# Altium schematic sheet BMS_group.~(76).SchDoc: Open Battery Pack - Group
size A3; Author: Morgane Vallée; Revision: 1.0; SheetNumber: 2; SheetTotal: 3
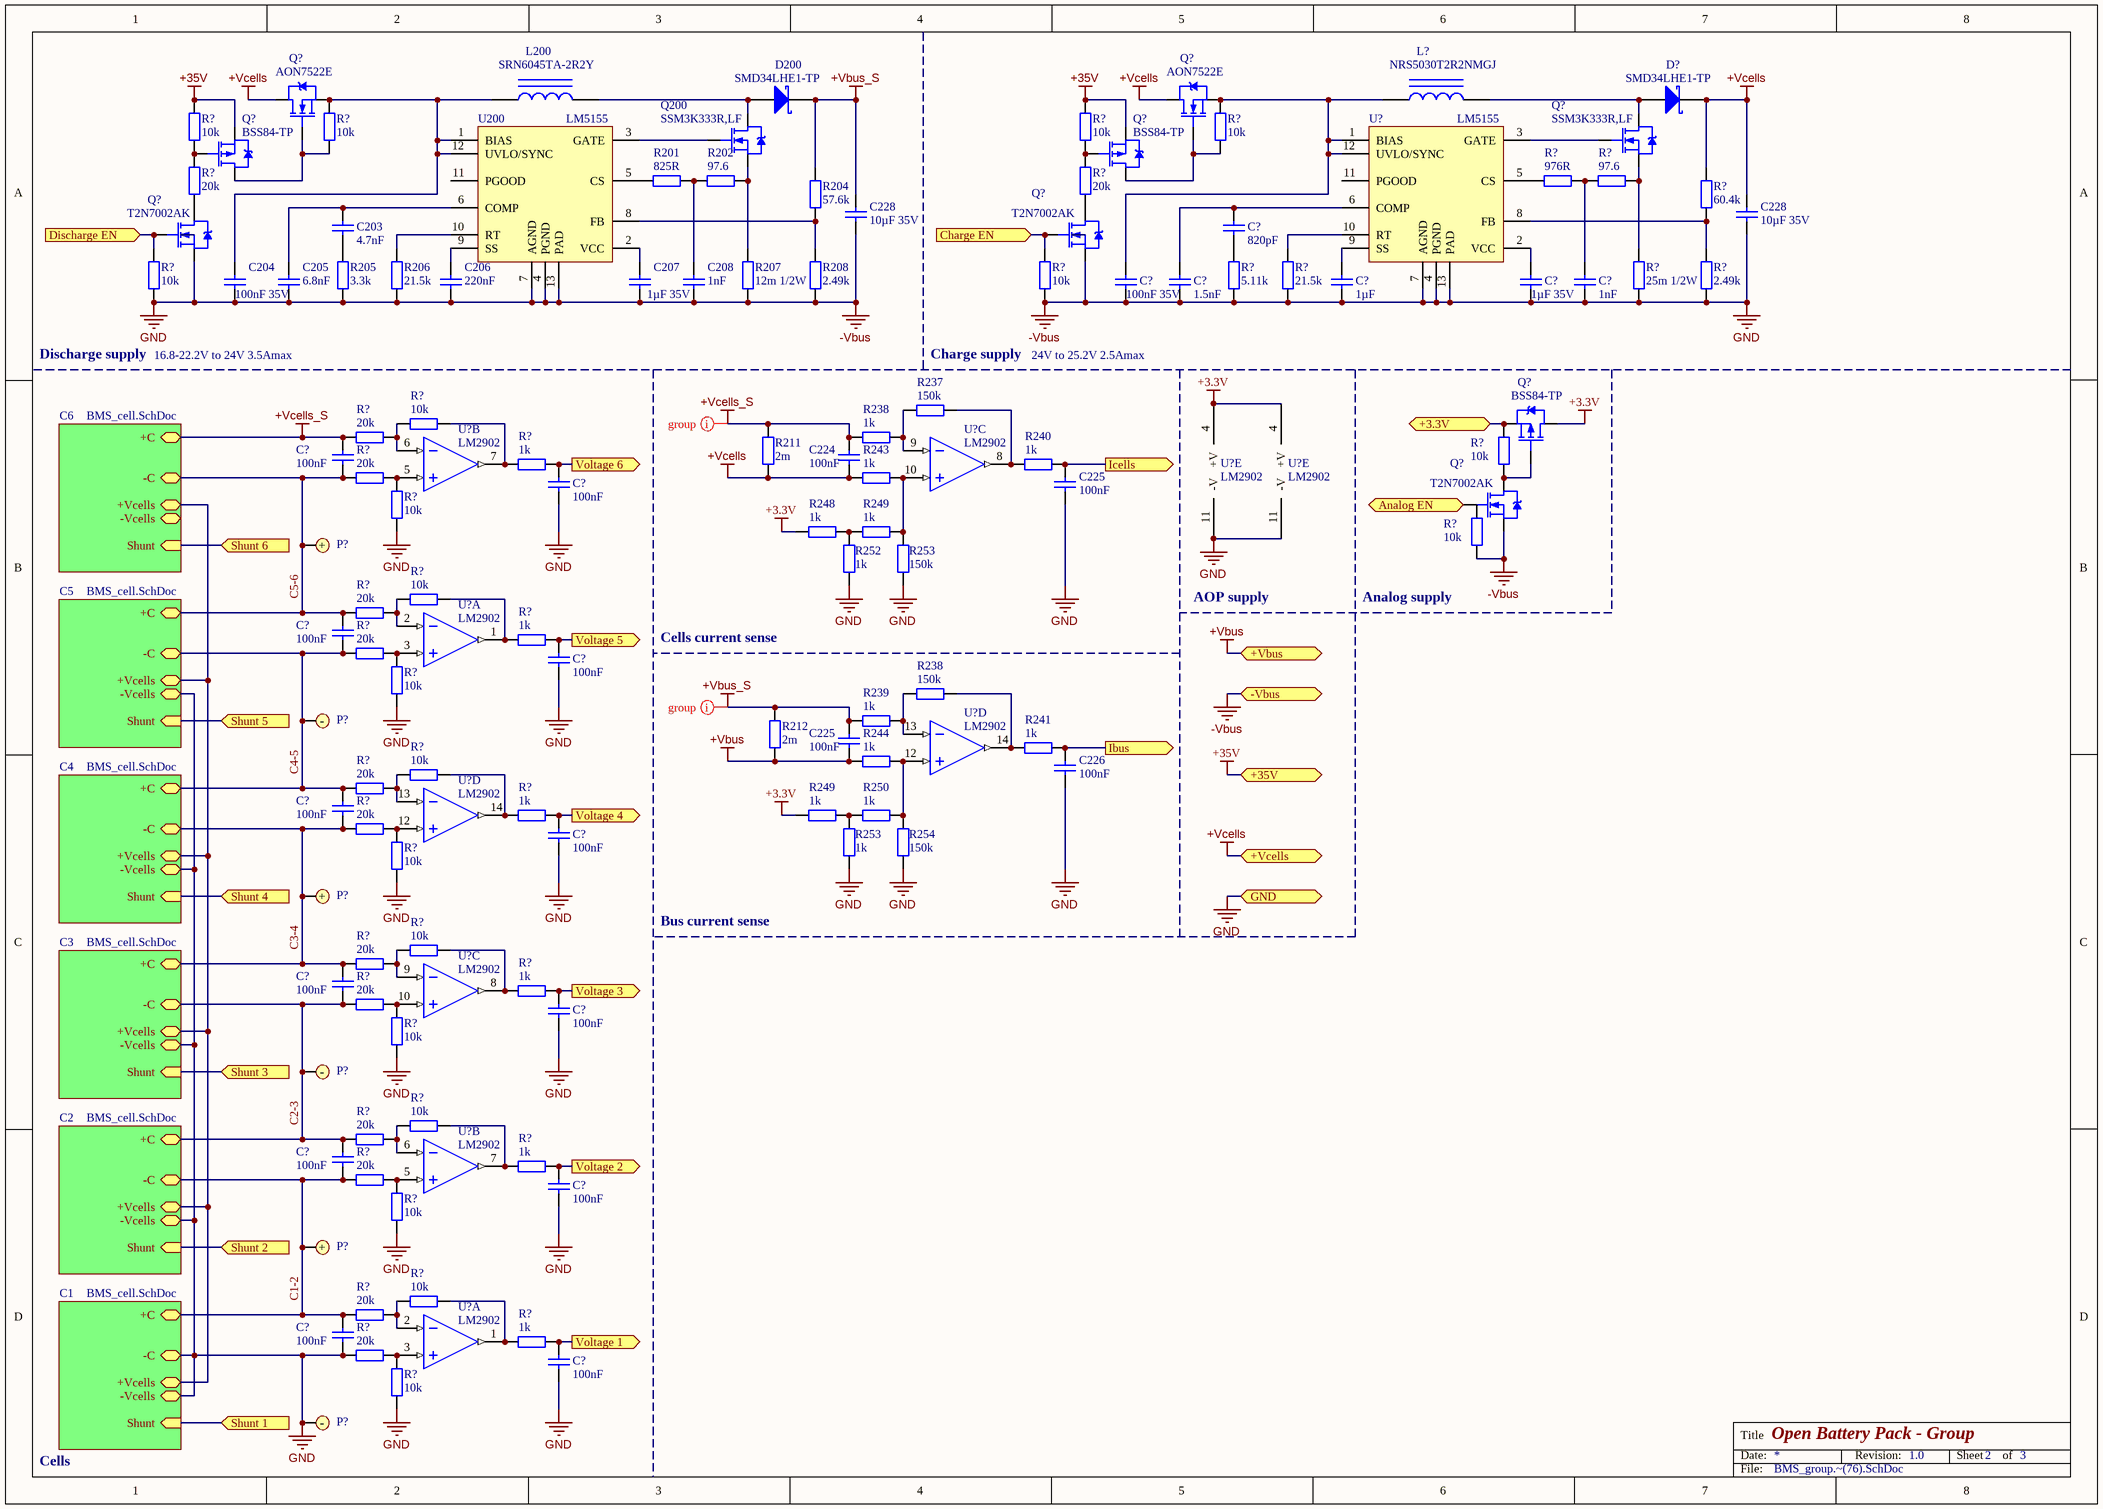
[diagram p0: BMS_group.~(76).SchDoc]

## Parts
(Parts that share a designator on the sheet are numbered #1, #2 ... from top to bottom, then left to right.)
C203  4.7nF  [C0603]
C204  100nF 35V  [C0603]
C205  6.8nF  [C0603]
C206  220nF  [C0603]
C207  1µF 35V  [C0805]
C208  1nF  [C0603]
C224  100nF  [C0603]
C225#1  100nF  [C0603]
C225#2  100nF  [C0603]
C226  100nF  [C0603]
C228#1  10µF 35V  [C0603]
C228#2  10µF 35V  [C0603]
C?#1  820pF  [C0603]
C?#2  100nF 35V  [C0603]
C?#3  1.5nF  [C0603]
C?#4  1µF  [C0603]
C?#5  1µF 35V  [C0805]
C?#6  1nF  [C0603]
C?#7  100nF  [C0603]
C?#8  100nF  [C0603]
C?#9  100nF  [C0603]
C?#10  100nF  [C0603]
C?#11  100nF  [C0603]
C?#12  100nF  [C0603]
C?#13  100nF  [C0603]
C?#14  100nF  [C0603]
C?#15  100nF  [C0603]
C?#16  100nF  [C0603]
C?#17  100nF  [C0603]
C?#18  100nF  [C0603]
D200  SMD34LHE1-TP  [SOD-123H]
D?  SMD34LHE1-TP  [SOD-123H]
L200  SRN6045TA-2R2Y  [SELF_SMD_8x8]
L?  NRS5030T2R2NMGJ  [SELF_SMD_8x8]
P?#1  Bat+  [Keystone 241]  (value not drawn)
P?#2  Bat-  [Keystone 2993]  (value not drawn)
P?#3  Bat+  [Keystone 241]  (value not drawn)
P?#4  Bat-  [Keystone 2993]  (value not drawn)
P?#5  Bat+  [Keystone 241]  (value not drawn)
P?#6  Bat-  [Keystone 2993]  (value not drawn)
Q200  SSM3K333R,LF  [TI SOT-23-3 DBZ]
Q?#1  AON7522E  [DIODES SOT-23-3]
Q?#2  AON7522E  [DIODES SOT-23-3]
Q?#3  SSM3K333R,LF  [TI SOT-23-3 DBZ]
Q?#4  BSS84-TP  [DIODES SOT-23-3]
Q?#5  BSS84-TP  [DIODES SOT-23-3]
Q?#6  T2N7002AK  [DIODES SOT-23-3]
Q?#7  T2N7002AK  [DIODES SOT-23-3]
Q?#8  BSS84-TP  [DIODES SOT-23-3]
Q?#9  T2N7002AK  [DIODES SOT-23-3]
R201  825R  [R0603]
R202  97.6  [R0603]
R204  57.6k  [R0603]
R205  3.3k  [R0603]
R206  21.5k  [R0603]
R207  12m 1/2W  [R1206]
R208  2.49k  [R0603]
R211  2m  [R1206]
R212  2m  [R1206]
R237  150k  [R0603]
R238#1  1k  [R0603]
R238#2  150k  [R0603]
R239  1k  [R0603]
R240  1k  [R0603]
R241  1k  [R0603]
R243  1k  [R0603]
R244  1k  [R0603]
R248  1k  [R0603]
R249#1  1k  [R0603]
R249#2  1k  [R0603]
R250  1k  [R0603]
R252  1k  [R0603]
R253#1  150k  [R0603]
R253#2  1k  [R0603]
R254  150k  [R0603]
R?#1  10k  [R0603]
R?#2  10k  [R0603]
R?#3  10k  [R0603]
R?#4  10k  [R0603]
R?#5  20k  [R0603]
R?#6  20k  [R0603]
R?#7  976R  [R0603]
R?#8  97.6  [R0603]
R?#9  60.4k  [R0603]
R?#10  10k  [R0603]
R?#11  10k  [R0603]
R?#12  5.11k  [R0603]
R?#13  21.5k  [R0603]
R?#14  25m 1/2W  [R1206]
R?#15  2.49k  [R0603]
R?#16  10k  [R0603]
R?#17  20k  [R0603]
R?#18  10k  [R0603]
R?#19  1k  [R0603]
R?#20  20k  [R0603]
R?#21  10k  [R0603]
R?#22  10k  [R0603]
R?#23  10k  [R0603]
R?#24  20k  [R0603]
R?#25  1k  [R0603]
R?#26  20k  [R0603]
R?#27  10k  [R0603]
R?#28  10k  [R0603]
R?#29  20k  [R0603]
R?#30  1k  [R0603]
R?#31  20k  [R0603]
R?#32  10k  [R0603]
R?#33  10k  [R0603]
R?#34  20k  [R0603]
R?#35  1k  [R0603]
R?#36  20k  [R0603]
R?#37  10k  [R0603]
R?#38  10k  [R0603]
R?#39  20k  [R0603]
R?#40  1k  [R0603]
R?#41  20k  [R0603]
R?#42  10k  [R0603]
R?#43  10k  [R0603]
R?#44  20k  [R0603]
R?#45  1k  [R0603]
R?#46  20k  [R0603]
R?#47  10k  [R0603]
U200  LM5155  [TI WSON-12]
U?#1  LM5155  [TI WSON-12]
U?#2  LM2902  [Atmel SO-14 14S1]  (part B of 5)
U?#3  LM2902  [Atmel SO-14 14S1]  (part C of 5)
U?#4  LM2902  [Atmel SO-14 14S1]  (part E of 5)
U?#5  LM2902  [Atmel SO-14 14S1]  (part E of 5)
U?#6  LM2902  [Atmel SO-14 14S1]  (part A of 5)
U?#7  LM2902  [Atmel SO-14 14S1]  (part D of 5)
U?#8  LM2902  [Atmel SO-14 14S1]  (part D of 5)
U?#9  LM2902  [Atmel SO-14 14S1]  (part C of 5)
U?#10  LM2902  [Atmel SO-14 14S1]  (part B of 5)
U?#11  LM2902  [Atmel SO-14 14S1]  (part A of 5)

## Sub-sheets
C1 = BMS_cell.SchDoc: -C, +C, +Vcells, -Vcells, Shunt (in)
C2 = BMS_cell.SchDoc: -C, +C, +Vcells, -Vcells, Shunt (in)
C3 = BMS_cell.SchDoc: -C, +C, +Vcells, -Vcells, Shunt (in)
C4 = BMS_cell.SchDoc: -C, +C, +Vcells, -Vcells, Shunt (in)
C5 = BMS_cell.SchDoc: -C, +C, +Vcells, -Vcells, Shunt (in)
C6 = BMS_cell.SchDoc: -C, +C, +Vcells, -Vcells, Shunt (in)

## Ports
+3.3V, +35V, +Vbus, +Vcells, -Vbus, Analog EN (in), Charge EN (in), Discharge EN (in), GND, Ibus (out), Icells (out), Shunt 1 (in), Shunt 2 (in), Shunt 3 (in), Shunt 4 (in), Shunt 5 (in), Shunt 6 (in), Voltage 1 (out), Voltage 2 (out), Voltage 3 (out), Voltage 4 (out), Voltage 5 (out), Voltage 6 (out)

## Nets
+3.3V: Q?#8.3(D) R248.2 R249#2.2 U?#4.4(+V) U?#5.4(+V)
+35V: Q?#4.2(S) Q?#5.2(S) R?#1.2 R?#3.2 ; port +35V
+Vbus: C225#2.2 R212.1 R244.2 ; port +Vbus
+Vbus_S: C225#2.1 C228#1.1 D200.3(K) R204.2 R212.2 R239.1
+Vcells: C224.2 C228#2.1 D?.3(K) Q?#1.3(D) Q?#2.3(D) R211.1 R243.2 R?#9.2 ; port +Vcells
+Vcells_S: C224.1 C?#7.1 R211.2 R238#1.1 R?#17.1 ; sheet C6/+C
-Vbus: C204.2 C205.2 C206.2 C207.2 C208.2 C225#1.2 C226.2 C228#1.2 C228#2.2 C?#2.2 C?#3.2 C?#4.2 C?#5.2 C?#6.2 C?#8.2 C?#10.2 C?#12.2 C?#14.2 C?#16.2 C?#17.2 C?#18.2 P?#6.1 Q?#6.2(S) Q?#7.2(S) Q?#9.2(S) R205.1 R206.1 R207.1 R208.1 R252.2 R253#1.1 R253#2.2 R254.1 R?#10.1 R?#11.1 R?#12.1 R?#13.1 R?#14.1 R?#15.1 R?#21.2 R?#22.1 R?#27.2 R?#32.2 R?#37.2 R?#42.2 R?#46.2 R?#47.2 U200.4(PGND) U200.7(AGND) U200.13(PAD) U?#1.4(PGND) U?#1.7(AGND) U?#1.13(PAD) U?#4.11(-V) U?#5.11(-V) ; port -Vbus, port GND, sheet C1/-C, sheet C1/-Vcells, sheet C2/-Vcells, sheet C3/-Vcells, sheet C4/-Vcells, sheet C5/-Vcells  [also labelled GND]
+3.3V: Q?#8.2(S) R?#18.1 ; port +3.3V  [a separate net that carries the same name]
Analog EN: Q?#9.1(G) ; port Analog EN
C1-2: C?#15.2 C?#17.1 P?#5.1 R?#41.2 R?#44.1 ; sheet C1/+C, sheet C2/-C
C2-3: C?#13.2 C?#15.1 P?#4.1 R?#36.2 R?#39.1 ; sheet C2/+C, sheet C3/-C
C3-4: C?#11.2 C?#13.1 P?#3.1 R?#31.2 R?#34.1 ; sheet C3/+C, sheet C4/-C
C4-5: C?#9.2 C?#11.1 P?#2.1 R?#26.2 R?#29.1 ; sheet C4/+C, sheet C5/-C
C5-6: C?#7.2 C?#9.1 P?#1.1 R?#20.2 R?#24.1 ; sheet C5/+C, sheet C6/-C
Charge EN: Q?#7.1(G) R?#11.2 ; port Charge EN
Discharge EN: Q?#6.1(G) R?#10.2 ; port Discharge EN
Ibus: C226.1 R241.1 ; port Ibus
Icells: C225#1.1 R240.1 ; port Icells
Shunt 1: port Shunt 1, sheet C1/Shunt
Shunt 2: port Shunt 2, sheet C2/Shunt
Shunt 3: port Shunt 3, sheet C3/Shunt
Shunt 4: port Shunt 4, sheet C4/Shunt
Shunt 5: port Shunt 5, sheet C5/Shunt
Shunt 6: port Shunt 6, sheet C6/Shunt
Voltage 1: C?#18.1 R?#45.1 ; port Voltage 1
Voltage 2: C?#16.1 R?#40.1 ; port Voltage 2
Voltage 3: C?#14.1 R?#35.1 ; port Voltage 3
Voltage 4: C?#12.1 R?#30.1 ; port Voltage 4
Voltage 5: C?#10.1 R?#25.1 ; port Voltage 5
Voltage 6: C?#8.1 R?#19.1 ; port Voltage 6
NetC203_1: C203.1 C205.1 U200.6(COMP)
NetC203_2: C203.2 R205.2
NetC204_1: C204.1 L200.1 Q?#1.2(S) R?#2.2 U200.1(BIAS) U200.12(UVLO/SYNC)
NetC206_1: C206.1 U200.9(SS)
NetC207_1: C207.1 U200.2(VCC)
NetC208_1: C208.1 R201.1 R202.2
NetC?#1_1: C?#1.1 C?#3.1 U?#1.6(COMP)
NetC?#1_2: C?#1.2 R?#12.2
NetC?#2_1: C?#2.1 L?.1 Q?#2.2(S) R?#4.2 U?#1.1(BIAS) U?#1.12(UVLO/SYNC)
NetC?#4_1: C?#4.1 U?#1.9(SS)
NetC?#5_1: C?#5.1 U?#1.2(VCC)
NetC?#6_1: C?#6.1 R?#7.1 R?#8.2
NetD200_1: D200.1(A) L200.2 Q200.3(D)
NetD?_1: D?.1(A) L?.2 Q?#3.3(D)
NetQ200_1: Q200.1(G) U200.3(GATE)
NetQ200_2: Q200.2(S) R202.1 R207.2
NetQ?#1_1: Q?#1.1(G) Q?#4.3(D) R?#2.1
NetQ?#2_1: Q?#2.1(G) Q?#5.3(D) R?#4.1
NetQ?#3_1: Q?#3.1(G) U?#1.3(GATE)
NetQ?#3_2: Q?#3.2(S) R?#8.1 R?#14.2
NetQ?#4_1: Q?#4.1(G) R?#1.1 R?#5.2
NetQ?#5_1: Q?#5.1(G) R?#3.1 R?#6.2
NetQ?#6_3: Q?#6.3(D) R?#5.1
NetQ?#7_3: Q?#7.3(D) R?#6.1
NetQ?#8_1: Q?#8.1(G) Q?#9.3(D) R?#18.2
NetR201_2: R201.2 U200.5(CS)
NetR204_1: R204.1 R208.2 U200.8(FB)
NetR206_2: R206.2 U200.10(RT)
NetR237_1: R237.1 R240.2 U?#3.8(OUT)
NetR237_2: R237.2 R238#1.2 U?#3.9(IN-)
NetR238#2_1: R238#2.1 R241.2 U?#7.14(OUT)
NetR238#2_2: R238#2.2 R239.2 U?#7.13(IN-)
NetR243_1: R243.1 R249#1.1 R253#1.2 U?#3.10(IN+)
NetR244_1: R244.1 R250.1 R254.2 U?#7.12(IN+)
NetR248_1: R248.1 R249#1.2 R252.1
NetR249#2_1: R249#2.1 R250.2 R253#2.1
NetR?#7_2: R?#7.2 U?#1.5(CS)
NetR?#9_1: R?#9.1 R?#15.2 U?#1.8(FB)
NetR?#13_2: R?#13.2 U?#1.10(RT)
NetR?#16_1: R?#16.1 R?#17.2 U?#2.6(IN-)
NetR?#16_2: R?#16.2 R?#19.2 U?#2.7(OUT)
NetR?#20_1: R?#20.1 R?#21.1 U?#2.5(IN+)
NetR?#23_1: R?#23.1 R?#24.2 U?#6.2(IN-)
NetR?#23_2: R?#23.2 R?#25.2 U?#6.1(OUT)
NetR?#26_1: R?#26.1 R?#27.1 U?#6.3(IN+)
NetR?#28_1: R?#28.1 R?#29.2 U?#8.13(IN-)
NetR?#28_2: R?#28.2 R?#30.2 U?#8.14(OUT)
NetR?#31_1: R?#31.1 R?#32.1 U?#8.12(IN+)
NetR?#33_1: R?#33.1 R?#34.2 U?#9.9(IN-)
NetR?#33_2: R?#33.2 R?#35.2 U?#9.8(OUT)
NetR?#36_1: R?#36.1 R?#37.1 U?#9.10(IN+)
NetR?#38_1: R?#38.1 R?#39.2 U?#10.6(IN-)
NetR?#38_2: R?#38.2 R?#40.2 U?#10.7(OUT)
NetR?#41_1: R?#41.1 R?#42.1 U?#10.5(IN+)
NetR?#43_1: R?#43.1 R?#44.2 U?#11.2(IN-)
NetR?#43_2: R?#43.2 R?#45.2 U?#11.1(OUT)
NetR?#46_1: R?#46.1 R?#47.1 U?#11.3(IN+)
(unnamed): sheet C1/+Vcells, sheet C2/+Vcells, sheet C3/+Vcells, sheet C4/+Vcells, sheet C5/+Vcells, sheet C6/+Vcells

Not connected (* = marked no-connect by the designer): R?#22 2; U200 11(PGOOD); U?#1 11(PGOOD)

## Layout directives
net class Group: +Vbus_S, +Vcells_S

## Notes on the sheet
- Discharge supply
- 16.8-22.2V to 24V 3.5Amax
- Charge supply
- 24V to 25.2V 2.5Amax
- Cells current sense
- AOP supply
- Analog supply
- Bus current sense
- Cells

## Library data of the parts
C203-C208 C224 C225#1 C225#2 C226 C228#1 C228#2 C?#1-C?#18 = Cap: Capacitor
D200 D? = Diode BAT17
L200 L? = Inductor Iron: Magnetic-Core Inductor
P?#1 P?#3 P?#5 = Bat+: Battery contact +
P?#2 P?#4 P?#6 = Bat-: Battery contact -
Q200 Q?#1-Q?#3 Q?#6 Q?#7 Q?#9 = MOSFET_N
Q?#4 Q?#5 Q?#8 = MOSFET_P
R201 R202 R204-R208 R211 R212 R237 R238#1 R238#2 R239-R241 R243 R244 R248 R249#1 R249#2 R250 R252 R253#1 R253#2 R254 R?#1-R?#47 = Res2: Resistor
U200 U?#1 = LM5155: 2.2-MHz Wide Input Nonsynchronous Boost, SEPIC, Flyback Controller
U?#2-U?#11 = LM2902: Low-power quad operational amplifiers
